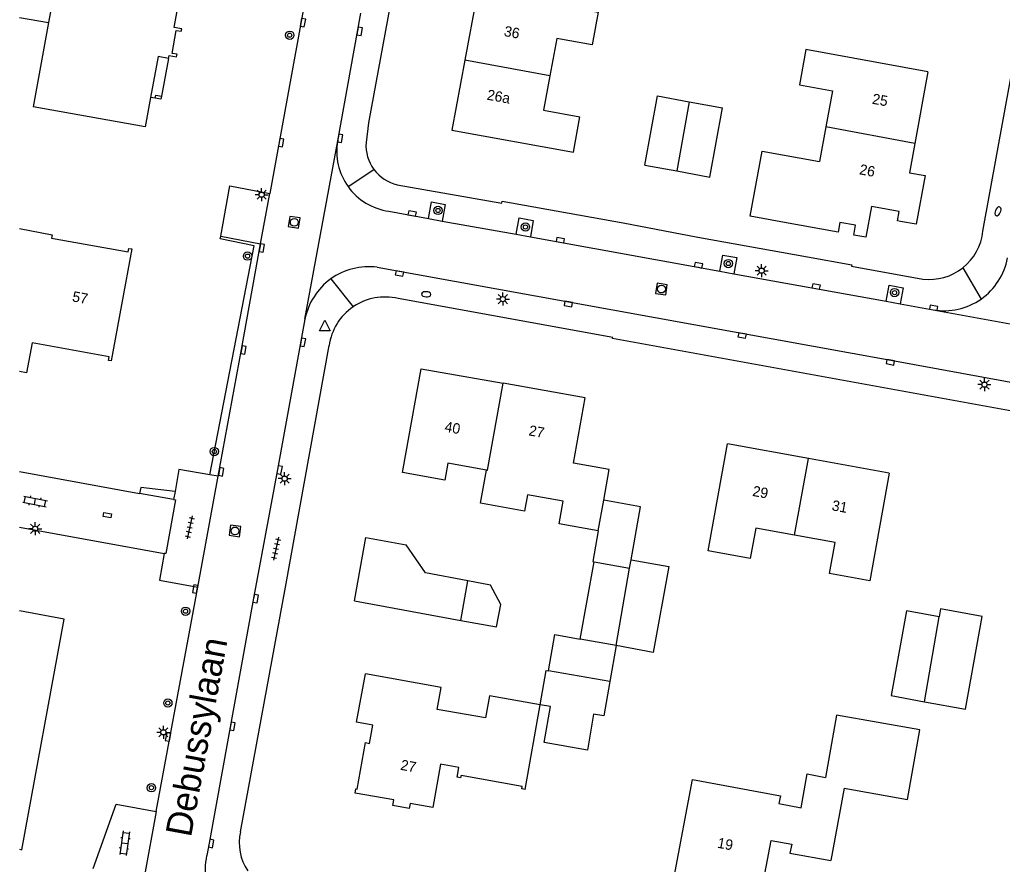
# Model space of a CAD drawing. Extents: x 132999 to 136000, y 398499 to 400501.
# Drawn here: x 133000 to 133094.4, y 399120.9 to 399202.1 of the extents above; entities that cross this region are included whole.
import ezdxf

# ---------------------------------------------------------------- set-up
doc = ezdxf.new("R2010")
doc.units = 0
for name, color, linetype in [('gg-afsc-haag', 7, 'Continuous'), ('gg-afsc-hekwerk', 7, 'Continuous'), ('gg-afsc-muur', 7, 'Continuous'), ('gg-anno-huisnummerreeks BGT', 7, 'Continuous'), ('gg-anno-openbare ruimte label', 7, 'Continuous'), ('gg-bbg-bijgebouw', 7, 'Continuous'), ('gg-bbg-gedigitaliseerde bebouwing', 7, 'Continuous'), ('gg-bbg-gedigitaliseerde bijgebouw', 7, 'Continuous'), ('gg-bbg-hoofdgebouw', 7, 'Continuous'), ('gg-bbg-luifel en loopbrug', 7, 'Continuous'), ('gg-bbg-onder overbouw', 7, 'Continuous'), ('gg-bbg-pand overbouw', 7, 'Continuous'), ('gg-bbg-pilaar onder overbouw', 7, 'Continuous'), ('gg-bbg-pilaar pand', 7, 'Continuous'), ('gg-bbg-tussenscheiding', 7, 'Continuous'), ('gg-knt-verharding', 7, 'Continuous'), ('gt-grn-groengrens', 7, 'Continuous'), ('gt-grn-vlakafsluiter', 7, 'Continuous'), ('gt-grn-weggrens', 7, 'Continuous'), ('gt-symb-boom', 7, 'Continuous'), ('gt-symb-brandkraan', 7, 'Continuous'), ('gt-symb-klinker verharding', 7, 'Continuous'), ('gt-symb-kolk', 7, 'Continuous'), ('gt-symb-kolk center center', 7, 'Continuous'), ('gt-symb-lichtmast', 7, 'Continuous'), ('gt-symb-rioolschacht', 7, 'Continuous'), ('gt-symb-tegel verharding', 7, 'Continuous'), ('gt-symb-waterafsluiter', 7, 'Continuous')]:
    doc.layers.add(name, color=color, linetype=linetype)

# ---------------------------------------------------------------- blocks, each defined once
blk = doc.blocks.new('gt0-BOOM')
at = {"layer": 'gt-symb-boom'}
for radius in [0.4, 0.2]:
    blk.add_circle((0, 0), radius, dxfattribs=at)
blk = doc.blocks.new('gt0-BR')
at = {"layer": 'gt-symb-brandkraan'}
for centre, radius, start, end in [((-0.244, 0), 0.206, 107.56694, 252.43307), ((0.599, -2.664), 3, 106.89205, 107.56694), ((0, -0.691), 0.938, 73.10799, 106.89205), ((-0.599, -2.664), 3, 72.43309, 73.10799), ((0.244, 0), 0.206, 287.56695, 72.43309), ((0.599, 2.664), 3, 252.43307, 253.10797), ((0, 0.691), 0.938, 253.10797, 286.89206), ((-0.599, 2.664), 3, 286.89206, 287.56695)]:
    blk.add_arc(centre, radius, start, end, dxfattribs=at)
blk = doc.blocks.new('gt0-KOLK')
at = {"layer": 'gt-symb-kolk'}
blk.add_lwpolyline([(0, 0), (0.375, 0), (0.375, 0.4), (-0.375, 0.4), (-0.375, 0), (0, 0)], dxfattribs=at)
blk = doc.blocks.new('gt0-RS')
at = {"layer": 'gt-symb-rioolschacht'}
blk.add_lwpolyline([(-0.5, -0.5), (0.5, -0.5), (0.5, 0.5), (-0.5, 0.5)], close=True, dxfattribs=at)
blk.add_circle((0, 0), 0.375, dxfattribs=at)
blk = doc.blocks.new('gt0-LMAST')
at = {"layer": 'gt-symb-lichtmast'}
for p, q in [((-0.182, 0.173), (-0.447, 0.438)), ((-0.005, 0.246), (-0.005, 0.621)), ((0.172, 0.173), (0.437, 0.438)), ((-0.255, -0.004), (-0.63, -0.004)), ((-0.182, -0.181), (-0.447, -0.446)), ((-0.005, -0.254), (-0.005, -0.629)), ((0.437, -0.446), (0.172, -0.181)), ((0.245, -0.004), (0.62, -0.004))]:
    blk.add_line(p, q, dxfattribs=at)
blk.add_circle((-0.005, -0.004), 0.25, dxfattribs=at)
blk = doc.blocks.new('gt0-WAFSL')
at = {"layer": 'gt-symb-waterafsluiter'}
for p, q in [((-0.5, -0.333), (0, 0.667)), ((0, 0.667), (0.5, -0.333)), ((0.5, -0.333), (-0.5, -0.333))]:
    blk.add_line(p, q, dxfattribs=at)
blk = doc.blocks.new('gt0-TEG1')
at = {"layer": 'gt-symb-tegel verharding'}
for p, q in [((-1.125, 0), (1.125, 0)), ((-0.9, -0.25), (-0.9, 0.25)), ((-0.45, -0.25), (-0.45, 0.25)), ((0, -0.25), (0, 0.25)), ((0.45, -0.25), (0.45, 0.25)), ((0.9, -0.25), (0.9, 0.25))]:
    blk.add_line(p, q, dxfattribs=at)
blk = doc.blocks.new('gt0-KOLKCC')
at = {"layer": 'gt-symb-kolk center center'}
blk.add_lwpolyline([(-0.375, 0.2), (0.375, 0.2), (0.375, -0.2), (-0.375, -0.2)], close=True, dxfattribs=at)
blk = doc.blocks.new('gt0-KL1')
at = {"layer": 'gt-symb-klinker verharding'}
for p, q in [((-1.15, 0.3), (1.15, 0.3)), ((-1, -0.3), (-1, 0.3)), ((-0.5, 0.3), (-0.5, 0.45)), ((0, -0.3), (0, 0.3)), ((0.5, 0.3), (0.5, 0.45)), ((1, -0.3), (1, 0.3)), ((-1.15, -0.3), (1.15, -0.3)), ((-0.5, -0.45), (-0.5, -0.3)), ((0.5, -0.45), (0.5, -0.3))]:
    blk.add_line(p, q, dxfattribs=at)

msp = doc.modelspace()

# ---------------------------------------------------------------- linework, layer by layer
at = {"layer": 'gg-afsc-haag'}
msp.add_lwpolyline([(133018.279, 399158.318), (133022.542, 399180.355), (133019.278, 399181.017), (133019.329, 399181.268)], dxfattribs=at)
at = {"layer": 'gg-afsc-hekwerk'}
msp.add_line((133046.37, 399184.633), (133057.999, 399182.556), dxfattribs=at)
at = {"layer": 'gg-afsc-muur'}
msp.add_line((133065.18, 399181.191), (133075.719, 399179.299), dxfattribs=at)
at = {"layer": 'gg-bbg-bijgebouw'}
for p, q in [((133060.087, 399188.109), (133063.171, 399187.54)), ((133063.171, 399187.54), (133066.318, 399186.96))]:
    msp.add_line(p, q, dxfattribs=at)
msp.add_lwpolyline([(133032.185, 399146.198), (133033.271, 399152.282), (133037.16, 399151.588)], dxfattribs=at)
at = {"layer": 'gg-bbg-gedigitaliseerde bebouwing'}
for p, q in [((133004.255, 399209.97), (133002.768, 399201.804)), ((133002.768, 399201.804), (133001.295, 399193.715)), ((133077.479, 399191.772), (133076.879, 399188.467)), ((133048.59, 399128.07), (133050.025, 399136.205)), ((133079.246, 399128.182), (133077.95, 399121.25)), ((133000, 399122.31), (133000.22, 399122.27))]:
    msp.add_line(p, q, dxfattribs=at)
for points in [[(133044.04, 399204.97), (133055.613, 399202.822), (133055.027, 399199.663), (133051.635, 399200.292), (133050.967, 399196.691)], [(133087.29, 399197.09), (133075.562, 399199.218), (133074.947, 399195.83), (133078.112, 399195.255), (133077.479, 399191.772)], [(133050.967, 399196.691), (133050.354, 399193.388), (133053.85, 399192.74)], [(133073.514, 399182.601), (133070.217, 399183.197), (133071.349, 399189.462), (133076.879, 399188.467)], [(133074.472, 399152.524), (133070.742, 399153.2), (133070.211, 399150.271), (133066.174, 399151.002), (133068.04, 399161.3)], [(133083.58, 399158.48), (133081.7, 399148.12), (133077.826, 399148.823), (133078.369, 399151.817), (133074.472, 399152.524)], [(133050.025, 399136.205), (133045.145, 399137.063), (133044.772, 399134.939), (133040.139, 399135.754), (133040.513, 399137.878), (133033.25, 399139.2)], [(133079.246, 399128.182), (133085.338, 399127.11), (133086.515, 399133.805), (133078.515, 399135.212), (133077.463, 399129.232)], [(133062.9, 399119.68), (133064.668, 399129.034), (133073.117, 399127.449), (133072.978, 399126.708), (133075.096, 399126.312), (133075.704, 399129.561), (133077.463, 399129.232)]]:
    msp.add_lwpolyline(points, dxfattribs=at)
at = {"layer": 'gg-bbg-gedigitaliseerde bijgebouw'}
for p, q in [((133060.087, 399188.109), (133061.315, 399194.771)), ((133061.315, 399194.771), (133064.363, 399194.205)), ((133064.363, 399194.205), (133067.545, 399193.615)), ((133066.318, 399186.96), (133067.545, 399193.615)), ((133053.872, 399142.531), (133055.231, 399149.96)), ((133055.231, 399149.96), (133058.628, 399149.338)), ((133058.628, 399149.338), (133058.771, 399150.154)), ((133042.398, 399144.33), (133043.074, 399148.12)), ((133032.185, 399146.198), (133042.398, 399144.33)), ((133057.331, 399141.901), (133056.729, 399138.453)), ((133056.729, 399138.453), (133050.819, 399139.484))]:
    msp.add_line(p, q, dxfattribs=at)
for points in [[(133043.074, 399148.12), (133039.015, 399148.895), (133037.16, 399151.588)], [(133058.771, 399150.154), (133062.392, 399149.494), (133060.89, 399141.252), (133057.331, 399141.901)], [(133088.384, 399144.671), (133085.234, 399145.244), (133083.752, 399137.087), (133086.973, 399136.5)], [(133086.973, 399136.5), (133090.894, 399135.786), (133092.516, 399144.693), (133088.514, 399145.422), (133088.384, 399144.671)], [(133050.819, 399139.484), (133051.425, 399142.958), (133053.872, 399142.531)]]:
    msp.add_lwpolyline(points, dxfattribs=at)
at = {"layer": 'gg-bbg-hoofdgebouw'}
for p, q in [((133044.04, 399204.97), (133042.785, 399198.21)), ((133087.29, 399197.09), (133086.037, 399190.184)), ((133075.808, 399159.89), (133068.04, 399161.3)), ((133083.58, 399158.48), (133075.808, 399159.89)), ((133055.616, 399152.947), (133056.142, 399155.891))]:
    msp.add_line(p, q, dxfattribs=at)
for points in [[(133014.296, 399198.373), (133014.354, 399198.658), (133015.086, 399198.506), (133015.134, 399198.758), (133014.647, 399198.846), (133015.044, 399201.059), (133015.539, 399200.97), (133015.583, 399201.212), (133014.837, 399201.349), (133016.01, 399207.757), (133009.549, 399208.919), (133009.56, 399208.978), (133004.255, 399209.97)], [(133042.785, 399198.21), (133041.531, 399191.45), (133053.23, 399189.34), (133053.85, 399192.74)], [(133012.589, 399194.614), (133012.07, 399191.775), (133001.295, 399193.715)], [(133086.037, 399190.184), (133085.526, 399187.369), (133087.014, 399187.099), (133086.164, 399182.427), (133084.664, 399182.692), (133084.36, 399182.742), (133084.524, 399183.647), (133081.866, 399184.13), (133081.328, 399181.167), (133080.162, 399181.381), (133080.329, 399182.316), (133078.84, 399182.583), (133078.67, 399181.655), (133073.514, 399182.601)], [(133000, 399181.998), (133003.11, 399181.41), (133003.05, 399181.08), (133010.44, 399179.75), (133010.5, 399180.08), (133010.77, 399180.04), (133008.81, 399169.28), (133008.54, 399169.33), (133008.6, 399169.68), (133001.19, 399171.03), (133000.67, 399168.13), (133000, 399168.25)], [(133044.865, 399158.786), (133041.144, 399159.45), (133040.852, 399157.816), (133036.806, 399158.538), (133038.59, 399168.53), (133046.468, 399167.124)], [(133056.142, 399155.891), (133056.669, 399158.844), (133053.223, 399159.459), (133054.34, 399165.72), (133046.468, 399167.124)], [(133055.616, 399152.947), (133051.856, 399153.618), (133052.242, 399155.784), (133048.806, 399156.397), (133048.527, 399154.832), (133044.294, 399155.587), (133044.865, 399158.786)], [(133000.22, 399122.27), (133004.27, 399144.45), (133000, 399145.252)], [(133048.59, 399128.07), (133048.26, 399128.13), (133048.3, 399128.35), (133042.42, 399129.4), (133042.38, 399129.19), (133042.06, 399129.24), (133042.22, 399130.18), (133040.46, 399130.49), (133039.72, 399126.34), (133037.52, 399126.73), (133037.43, 399126.24), (133035.88, 399126.53), (133035.97, 399127.07), (133032.25, 399127.72), (133032.32, 399128.13), (133032.43, 399128.11), (133033.25, 399132.57), (133033.621, 399132.48), (133033.94, 399134.24), (133032.39, 399134.53), (133033.25, 399139.2)], [(133062.9, 399119.68), (133071.28, 399118.11), (133072.22, 399123.16), (133074.21, 399122.8), (133074.031, 399121.95), (133077.95, 399121.25)]]:
    msp.add_lwpolyline(points, dxfattribs=at)
at = {"layer": 'gg-bbg-luifel en loopbrug'}
msp.add_line((133000, 399202.308), (133002.768, 399201.804), dxfattribs=at)
for points in [[(133058.771, 399150.154), (133059.682, 399155.258), (133056.142, 399155.891)], [(133055.616, 399152.947), (133055.087, 399149.986), (133055.231, 399149.96)], [(133042.398, 399144.33), (133045.841, 399143.7), (133046.237, 399145.864), (133045.238, 399147.724), (133043.074, 399148.12)], [(133050.025, 399136.205), (133050.604, 399139.522), (133050.819, 399139.484)], [(133056.729, 399138.453), (133056.151, 399135.136), (133055.165, 399135.308), (133054.564, 399131.86), (133050.408, 399132.585), (133051.01, 399136.033), (133050.025, 399136.205)]]:
    msp.add_lwpolyline(points, dxfattribs=at)
at = {"layer": 'gg-bbg-onder overbouw'}
msp.add_lwpolyline([(133014.296, 399198.373), (133013.309, 399198.548), (133012.589, 399194.614)], dxfattribs=at)
at = {"layer": 'gg-bbg-pand overbouw'}
for p, q in [((133014.296, 399198.373), (133013.635, 399194.744)), ((133013.022, 399194.535), (133012.589, 399194.614))]:
    msp.add_line(p, q, dxfattribs=at)
at = {"layer": 'gg-bbg-pilaar onder overbouw'}
msp.add_lwpolyline([(133013.022, 399194.535), (133013.084, 399194.846), (133013.635, 399194.744)], dxfattribs=at)
at = {"layer": 'gg-bbg-pilaar pand'}
msp.add_lwpolyline([(133013.635, 399194.744), (133013.573, 399194.433), (133013.022, 399194.535)], dxfattribs=at)
at = {"layer": 'gg-bbg-tussenscheiding'}
for p, q in [((133050.967, 399196.691), (133042.785, 399198.21)), ((133064.363, 399194.205), (133063.171, 399187.54)), ((133086.037, 399190.184), (133077.479, 399191.772)), ((133074.472, 399152.524), (133075.808, 399159.89)), ((133057.331, 399141.901), (133058.628, 399149.338)), ((133086.973, 399136.5), (133088.384, 399144.671)), ((133057.331, 399141.901), (133053.872, 399142.531))]:
    msp.add_line(p, q, dxfattribs=at)
msp.add_lwpolyline([(133044.865, 399158.786), (133044.975, 399158.766), (133046.468, 399167.124)], dxfattribs=at)
at = {"layer": 'gg-knt-verharding'}
for p, q in [((133092.585, 399181.75), (133102.168, 399234.622)), ((133027.369, 399203.685), (133024.038, 399185.368)), ((133030.566, 399190.453), (133032.789, 399202.712)), ((133023.154, 399180.544), (133024.038, 399185.368)), ((133035.486, 399183.67), (133039.289, 399182.967)), ((133039.289, 399182.967), (133040.619, 399182.729)), ((133040.619, 399182.729), (133047.727, 399181.453)), ((133057.999, 399182.556), (133065.18, 399181.191)), ((133019.329, 399181.268), (133023.154, 399180.544)), ((133047.727, 399181.453), (133049.084, 399181.209)), ((133049.084, 399181.209), (133067.294, 399177.902)), ((133067.294, 399177.902), (133068.644, 399177.659)), ((133068.644, 399177.659), (133083.289, 399175.01)), ((133083.289, 399175.01), (133084.628, 399174.766)), ((133084.628, 399174.766), (133087.812, 399174.187)), ((133000, 399158.628), (133011.533, 399156.541)), ((133017.12, 399147.53), (133019.078, 399158.181)), ((133019.078, 399158.181), (133018.279, 399158.318)), ((133014.802, 399155.95), (133011.533, 399156.541)), ((133014.934, 399156.722), (133014.802, 399155.95)), ((133000, 399153.286), (133013.904, 399150.767)), ((133013.136, 399125.933), (133017.12, 399147.53)), ((133009.279, 399126.649), (133013.136, 399125.933))]:
    msp.add_line(p, q, dxfattribs=at)
for points in [[(133037.247, 399212.401), (133033.537, 399192.164), (133033.291, 399190.264)], [(133019.329, 399181.268), (133020.213, 399186.124), (133024.038, 399185.368)], [(133036.288, 399186.208), (133046.339, 399184.453), (133046.37, 399184.633)], [(133039.289, 399182.967), (133039.576, 399184.566), (133040.905, 399184.323), (133040.619, 399182.729)], [(133047.727, 399181.453), (133048.01, 399183.031), (133049.367, 399182.783), (133049.084, 399181.209)], [(133019.078, 399158.181), (133021.319, 399170.37), (133023.154, 399180.544)], [(133067.294, 399177.902), (133067.574, 399179.457), (133068.927, 399179.23), (133068.644, 399177.659)], [(133075.719, 399179.299), (133079.971, 399178.507), (133079.963, 399178.399), (133086.801, 399177.153)], [(133034.355, 399178.281), (133083.726, 399169.34), (133139.191, 399159.193)], [(133083.289, 399175.01), (133083.569, 399176.548), (133084.907, 399176.302), (133084.628, 399174.766)], [(133187.008, 399146.493), (133186.762, 399146.936), (133185.994, 399147.608), (133185.074, 399148.035), (133184.1, 399148.308), (133139.809, 399156.359), (133056.989, 399171.443), (133057.003, 399171.522), (133036.364, 399175.27)], [(133027.423, 399173.276), (133024.788, 399158.819), (133022.491, 399146.453), (133018.208, 399122.908), (133017.974, 399121.708)], [(133021.235, 399124.001), (133025.555, 399147.519), (133029.747, 399170.748)], [(133018.279, 399158.318), (133015.293, 399158.829), (133014.934, 399156.722)], [(133014.802, 399155.95), (133014.966, 399155.921), (133014.037, 399150.743), (133013.904, 399150.767)], [(133013.904, 399150.767), (133013.445, 399148.187), (133017.12, 399147.53)], [(133013.136, 399125.933), (133011.997, 399119.8), (133011.98, 399119.625)]]:
    msp.add_lwpolyline(points, dxfattribs=at)
for centre, radius, start, end in [((133036.298, 399189.432), 5.822, 169.90086, 215.68637), ((133037.219, 399190.032), 3.935, 176.6232, 216.47655), ((133037.219, 399190.029), 3.933, 216.4431, 256.30713), ((133036.293, 399189.432), 5.818, 215.70841, 262.02481), ((133087.433, 399182.291), 5.18, 308.50195, 354.00551), ((133088.841, 399180.304), 6.201, 305.00928, 349.57737), ((133033.545, 399172.099), 6.235, 82.53951, 125.82908), ((133087.437, 399182.292), 5.178, 262.93989, 308.45588), ((133033.553, 399172.095), 6.242, 125.85729, 169.09141), ((133035.089, 399170.032), 5.391, 76.32256, 124.34554), ((133035.09, 399170.033), 5.39, 124.35189, 172.37663), ((133088.837, 399180.31), 6.208, 260.49989, 305.0071), ((133025.794, 399122.89), 4.692, 166.29781, 214.57096), ((133024.287, 399120.331), 6.462, 167.69585, 212.90146)]:
    msp.add_arc(centre, radius, start, end, dxfattribs=at)
at = {"layer": 'gt-grn-groengrens'}
msp.add_lwpolyline([(133014.934, 399156.722), (133011.633, 399157.093), (133011.533, 399156.541)], dxfattribs=at)
at = {"layer": 'gt-grn-vlakafsluiter'}
msp.add_line((133007.07, 399120.479), (133009.279, 399126.649), dxfattribs=at)
at = {"layer": 'gt-grn-weggrens'}
for p, q in [((133027.423, 399173.276), (133030.566, 399190.453)), ((133031.569, 399186.036), (133034.055, 399187.693)), ((133090.658, 399178.237), (133092.398, 399175.225)), ((133029.896, 399177.154), (133032.048, 399174.483)), ((133087.812, 399174.187), (133104.707, 399171.105))]:
    msp.add_line(p, q, dxfattribs=at)

# ---------------------------------------------------------------- block references
at = {"layer": 'gt-symb-boom'}
for p in [(133025.957, 399200.598), (133040.211, 399183.747), (133048.614, 399182.15), (133021.906, 399179.355), (133068.107, 399178.638), (133084.089, 399175.845), (133018.705, 399160.56), (133015.945, 399145.207), (133014.242, 399136.384), (133012.665, 399128.232)]:
    msp.add_blockref('gt0-BOOM', p, dxfattribs=at)
at = {"layer": 'gt-symb-brandkraan'}
for p, rotation in [((133094.025, 399183.655), 65.8392225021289), ((133039.075, 399175.688), -3.100155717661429)]:
    msp.add_blockref('gt0-BR', p, dxfattribs=dict(at, rotation=rotation))
at = {"layer": 'gt-symb-klinker verharding'}
for p, rotation in [((133001.477, 399155.751), -11.073871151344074), ((133010.093, 399122.905), -97.87092049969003)]:
    msp.add_blockref('gt0-KL1', p, dxfattribs=dict(at, rotation=rotation))
at = {"layer": 'gt-symb-kolk'}
for p, rotation in [((133027.032, 399201.844), -100.26370230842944), ((133032.483, 399201.017), -100.23844255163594), ((133024.942, 399190.302), -100.38568294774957), ((133030.615, 399190.726), -100.28752391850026), ((133037.692, 399183.254), -10.689550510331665), ((133051.931, 399180.698), -10.181417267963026), ((133023.087, 399180.177), -100.22255922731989), ((133065.211, 399178.277), -10.328665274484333), ((133036.544, 399177.884), 169.73629769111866), ((133076.52, 399176.241), -10.205244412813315), ((133052.77, 399174.947), 169.74567571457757), ((133087.812, 399174.187), -10.31278647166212), ((133069.477, 399171.925), 169.72041621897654), ((133021.319, 399170.37), -100.41888787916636), ((133027.031, 399171.088), -100.14822015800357), ((133083.726, 399169.34), 169.6222545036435), ((133019.165, 399158.65), -100.46796671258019), ((133024.788, 399158.819), -100.3618693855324), ((133017.068, 399147.297), 79.6222545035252), ((133022.491, 399146.453), -100.51704406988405), ((133020.258, 399134.172), -100.30484646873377), ((133014.463, 399133.08), 79.48295593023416), ((133018.208, 399122.908), -100.31278647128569)]:
    msp.add_blockref('gt0-KOLK', p, dxfattribs=dict(at, rotation=rotation))
at = {"layer": 'gt-symb-kolk center center', "rotation": 169.77744077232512}
msp.add_blockref('gt0-KOLKCC', (133008.43, 399154.449), dxfattribs=at)
at = {"layer": 'gt-symb-lichtmast'}
for p in [(133023.259, 399185.261), (133071.318, 399177.957), (133046.451, 399175.22), (133092.734, 399167), (133025.471, 399157.958), (133001.504, 399153.135), (133013.819, 399133.563)]:
    msp.add_blockref('gt0-LMAST', p, dxfattribs=at)
at = {"layer": 'gt-symb-rioolschacht'}
for p, rotation in [((133026.392, 399182.605), 171.2421801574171), ((133061.682, 399176.184), -8.162057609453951), ((133020.693, 399152.929), -98.39829097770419)]:
    msp.add_blockref('gt0-RS', p, dxfattribs=dict(at, rotation=rotation))
at = {"layer": 'gt-symb-tegel verharding'}
for p, rotation in [((133016.339, 399153.274), -102.53502334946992), ((133024.631, 399151.228), -102.53502335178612)]:
    msp.add_blockref('gt0-TEG1', p, dxfattribs=dict(at, rotation=rotation))
at = {"layer": 'gt-symb-waterafsluiter'}
msp.add_blockref('gt0-WAFSL', (133029.333, 399172.516), dxfattribs=at)

# ---------------------------------------------------------------- texts
at = {"layer": 'gg-anno-huisnummerreeks BGT'}
for s, rotation, p in [('36', 349.5, (133046.493, 399200.527)), ('26a', 349.8, (133044.854, 399194.406)), ('25', 349.7, (133081.878, 399194.017)), ('26', 349.7, (133080.647, 399187.231)), ('57', 349.7, (133004.999, 399175.009)), ('40', 349.9, (133040.786, 399162.492)), ('27', 349.9, (133048.87, 399162.124)), ('29', 349.7, (133070.374, 399156.303)), ('31', 349.7, (133078.003, 399154.919)), ('27', 349.4, (133036.544, 399129.967)), ('19', 349.4, (133066.995, 399122.474))]:
    msp.add_text(s, height=1, rotation=rotation, dxfattribs=at).set_placement(p)
at = {"layer": 'gg-anno-openbare ruimte label'}
msp.add_text('Debussylaan', height=2.5, rotation=79.5, dxfattribs=at).set_placement((133016.461, 399123.4))

doc.saveas('drawing.dxf')
